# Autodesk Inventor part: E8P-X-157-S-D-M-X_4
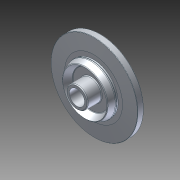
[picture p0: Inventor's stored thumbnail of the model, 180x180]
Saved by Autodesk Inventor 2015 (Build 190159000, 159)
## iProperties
Created: 2012-07
Part Number: E8P-X-157-S-D-M-X_4
Material: PC/ABS-Kunststoff
Document SubType Name: Modeling
Designer: rYan
Density: 0.357273 g/cm^3
Mass: 0.246055 g
Surface Area: 12.4844 cm^2
Volume: 0.688704 cm^3
Appearance: Glatt - weiß
Author: rYan
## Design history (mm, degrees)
node "E8P-X-157-S-D-M-X_41"
node "E8P-X-157-S-D-M-X_4"
node "Basis1"
